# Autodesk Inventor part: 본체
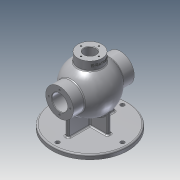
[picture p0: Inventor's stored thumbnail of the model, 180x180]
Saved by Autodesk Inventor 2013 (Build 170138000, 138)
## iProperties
Created: 2020-08
Part Number: 본체
Material: 알루미늄 6061
Document SubType Name: Modeling
Designer: 19
Density: 2.71 g/cm^3
Mass: 1759.16 g
Surface Area: 1342.42 cm^2
Volume: 649.136 cm^3
Author: 19
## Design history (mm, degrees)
sketch "스케치1"
  geometry: L1 (17.289, -50.101)-(-17.289, 50.101); A1 r 53 centre (0, 0) between (17.289, -50.101) and (-17.289, 50.101); 1 further point
  constraints: 2 end point, 2 point on circle, 1 centre point, 1 coincident, 1 midpoint
  dimensions: "d0" = 53 radius of A1
revolve "회전1" sketch "스케치1" stored, may be unused: angle "d1" = 90 deg
node "작업 평면1"
sketch "스케치2"
  geometry: C1 r 31 at (0, 0); 1 further point
  constraints: 1 centre point, 1 coincident
  dimensions: "d3" = 62 diameter of C1
extrude "돌출1" join sketch "스케치2" stored distance "d4" = 10; taper "d5" = 0 deg
sketch "스케치3"
  geometry: C1 r 31 at (0, 0) reference; C2 r 17.5 at (0, 0)
  constraints: 1 centre point, 1 coincident
  dimensions: "d6" = 35 diameter of C2
extrude "돌출2" cut sketch "스케치3" stored distance "d8" = 10; taper "d9" = 0 deg
sketch "스케치4" dims "d11" = 48
  geometry: C1 r 17.5 at (0, 0) reference; C2 r 31 at (0, 0) reference; 2 further points
  constraints: 3 coincident, 2 vertical alignment, 2 other
hole "구멍1" sketch "스케치4" at (0, 24) diameter "d12" = 3.242; stored, may be unused: countersink angle "d16" = 90 deg, drill point angle "d18" = 118 deg; dims "d13" = 12, "d14" = 4, "d15" = 2, "d17" = 15
sketch "스케치5"
  geometry: L1 (-68, 31)-(-42.988, 31) reference; L2 (42.988, 31)-(68, 31) reference; L3 (68, 31)-(68, 25.621) reference; L4 (68, 25.621)-(53, 25.621) reference; L5 (53, 25.621)-(52.026, 24) reference; L6 (52.026, 24)-(53, 22.379) reference; L7 (53, 22.379)-(68, 22.379) reference; L8 (68, 22.379)-(68, 17.5) reference; L9 (68, 17.5)-(-68, 17.5) reference; L10 (-68, 17.5)-(-68, 22.379) reference; L11 (-68, 22.379)-(-53, 22.379) reference; L12 (-53, 22.379)-(-52.026, 24) reference; L13 (-52.026, 24)-(-53, 25.621) reference; L14 (-53, 25.621)-(-68, 25.621) reference; L15 (-68, 25.621)-(-68, 31) reference; L16 (-42.988, -31)-(-68, -31) reference; L17 (-68, -31)-(-68, -25.621) reference; L18 (-68, -25.621)-(-53, -25.621) reference; L19 (-53, -25.621)-(-52.026, -24) reference; L20 (-52.026, -24)-(-53, -22.379) reference; L21 (-53, -22.379)-(-68, -22.379) reference; L22 (-68, -22.379)-(-68, -17.5) reference; L23 (-68, -17.5)-(68, -17.5) reference; L24 (68, -17.5)-(68, -22.379) reference; L25 (68, -22.379)-(53, -22.379) reference; L26 (53, -22.379)-(52.026, -24) reference; L27 (52.026, -24)-(53, -25.621) reference; L28 (53, -25.621)-(68, -25.621) reference; L29 (68, -25.621)-(68, -31) reference; L30 (68, -31)-(42.988, -31) reference; L31 (19.526, -38.311)-(-19.526, 38.311); A1 r 53 centre (0, 0) between (42.988, 31) and (0, 53) reference; A2 r 53 centre (0, 0) between (0, 53) and (-42.988, 31) reference; A3 r 53 centre (0, 0) between (-42.988, -31) and (0, -53) reference; A4 r 53 centre (0, 0) between (0, -53) and (42.988, -31) reference; A5 r 43 centre (0, 0) between (19.526, -38.311) and (-19.526, 38.311); 1 further point
  constraints: 2 end point, 2 point on circle, 1 centre point, 1 coincident, 1 midpoint
  dimensions: "d22" = 43 radius of A5
revolve "회전2" sketch "스케치5" stored, may be unused: angle "d23" = 90 deg
sketch "스케치6"
  geometry: L1 (-68, 31)-(-42.988, 31) reference; L2 (42.988, 31)-(68, 31) reference; L3 (68, 31)-(68, 25.621) reference; L4 (68, 25.621)-(53, 25.621) reference; L5 (53, 25.621)-(52.026, 24) reference; L6 (52.026, 24)-(53, 22.379) reference; L7 (53, 22.379)-(68, 22.379) reference; L8 (68, 22.379)-(68, 17.5) reference; L9 (68, 17.5)-(39.278, 17.5) reference; L10 (-39.278, 17.5)-(-68, 17.5) reference; L11 (-68, 17.5)-(-68, 22.379) reference; L12 (-68, 22.379)-(-53, 22.379) reference; L13 (-53, 22.379)-(-52.026, 24) reference; L14 (-52.026, 24)-(-53, 25.621) reference; L15 (-53, 25.621)-(-68, 25.621) reference; L16 (-68, 25.621)-(-68, 31) reference; L17 (-42.988, -31)-(-68, -31) reference; L18 (-68, -31)-(-68, -25.621) reference; L19 (-68, -25.621)-(-53, -25.621) reference; L20 (-53, -25.621)-(-52.026, -24) reference; L21 (-52.026, -24)-(-53, -22.379) reference; L22 (-53, -22.379)-(-68, -22.379) reference; L23 (-68, -22.379)-(-68, -17.5) reference; L24 (-68, -17.5)-(-39.278, -17.5) reference; L25 (39.278, -17.5)-(68, -17.5) reference; L26 (68, -17.5)-(68, -22.379) reference; L27 (68, -22.379)-(53, -22.379) reference; L28 (53, -22.379)-(52.026, -24) reference; L29 (52.026, -24)-(53, -25.621) reference; L30 (53, -25.621)-(68, -25.621) reference; L31 (68, -25.621)-(68, -31) reference; L32 (68, -31)-(42.988, -31) reference; L33 (-68, -17.5)-(-68, 17.5) reference; L34 (68, 17.5)-(68, -17.5) reference; L35 (-68, 0)-(68, 0); L36 (-52, 0)-(-52, 18.5); L37 (-52, 18.5)-(-50.25, 18.5); L38 (-50.25, 18.5)-(-50.25, 0); A1 r 53 centre (0, 0) between (42.988, 31) and (0, 53) reference; A2 r 53 centre (0, 0) between (0, 53) and (-42.988, 31) reference; A3 r 43 centre (0, 0) between (39.278, 17.5) and (0, 43) reference; A4 r 43 centre (0, 0) between (0, 43) and (-39.278, 17.5) reference; A5 r 43 centre (0, 0) between (-39.278, -17.5) and (0, -43) reference; A6 r 43 centre (0, 0) between (0, -43) and (39.278, -17.5) reference; A7 r 53 centre (0, 0) between (-42.988, -31) and (0, -53) reference; A8 r 53 centre (0, 0) between (0, -53) and (42.988, -31) reference; 1 further point
  constraints: 8 end point, 2 midpoint, 2 perpendicular, 2 point on line, 1 parallel
  dimensions: "d24" = 37 diameter of L37 L35; "d26" = 1.75 distance of L36.end L37.end; "d27" = 16 distance between parallel lines of L36 L33
revolve "회전3" sketch "스케치6" stored, may be unused: angle "d28" = 90 deg
node "작업 평면2"
sketch "스케치7"
  geometry: C1 r 27 at (0, 0); 1 further point
  constraints: 1 centre point, 1 coincident
  dimensions: "d30" = 54 diameter of C1
extrude "돌출3" join sketch "스케치7" stored distance "d31" = 10; taper "d32" = 0 deg
sketch "스케치8"
  geometry: C1 r 27 at (0, 0) reference; C2 r 13 at (0, 0)
  constraints: 1 centre point, 1 coincident
  dimensions: "d33" = 26 diameter of C2
extrude "돌출4" cut sketch "스케치8" stored distance "d34" = 10; taper "d35" = 0 deg
sketch "스케치9" dims "d36" = 40
  geometry: C1 r 13 at (0, 0) reference; C2 r 27 at (0, 0) reference; 2 further points
  constraints: 3 coincident, 2 vertical alignment, 2 other
hole "구멍2" sketch "스케치9" at (0, 20) diameter "d37" = 3.242; stored, may be unused: countersink angle "d41" = 90 deg, drill point angle "d43" = 118 deg; dims "d38" = 12, "d39" = 4, "d40" = 2, "d42" = 15
node "작업 평면3"
sketch "스케치10"
  geometry: C1 r 85 at (0, 0); 1 further point
  constraints: 1 centre point, 1 coincident
  dimensions: "d48" = 170 diameter of C1
extrude "돌출5" join sketch "스케치10" distance "d49" = 10; taper "d50" = 0 deg
sketch "스케치11"
  geometry: L1 (-31, 42.988)-(31, 42.988) reference; L2 (31, -42.988)-(-31, -42.988) reference; L3 (31, 68)-(-31, 68) reference; L4 (-31, 42.988)-(31, 42.988) reference; L5 (31, -68)-(-31, -68) reference; L6 (31, -42.988)-(-31, -42.988) reference; L7 (-43, 4)-(43, 4); L8 (43, 4)-(43, -4); L9 (43, -4)-(-43, -4); L10 (-43, -4)-(-43, 4); C1 r 85 at (0, 0) reference; C2 r 85 at (0, 0) reference; C3 r 27 at (0, 0) reference; C4 r 85 at (0, 0) reference; 5 further points
  constraints: 8 end point, 2 midpoint, 2 parallel, 1 horizontal, 1 horizontal alignment, 1 perpendicular, 1 vertical alignment, 1 other
  dimensions: "d51" = 86 distance of L8.end L9.end; "d53" = 8 distance of L9.end L7.start
extrude "돌출6" join sketch "스케치11" stored distance "d54" = 10; taper "d55" = 0 deg
sketch "스케치12"
  geometry: L1 (-4, 52)-(4, 52); L2 (4, 52)-(4, -52); L3 (4, -52)-(-4, -52); L4 (-4, -52)-(-4, 52); C1 r 85 at (0, 0) reference; 2 further points
  constraints: 8 end point, 2 midpoint, 2 parallel, 1 horizontal, 1 horizontal alignment, 1 perpendicular, 1 vertical alignment
  dimensions: "d56" = 104 distance of L1.end L2.end; "d58" = 8 distance of L1.start L1.end
extrude "돌출7" join sketch "스케치12" stored distance "d59" = 10; taper "d60" = 0 deg
node "작업 평면4"
chamfer "모따기1" distance "d77" = 1; stored, may be unused: second distance "d78" = 2, angle "d79" = 45 deg
fillet "모깎기1" dims "d80" = 3
fillet "모깎기2" dims "d81" = 3
fillet "모깎기3" dims "d82" = 3
fillet "모깎기4" dims "d83" = 3
fillet "모깎기5" dims "d84" = 3
node "작업 평면5"
sketch "스케치15"
  geometry: L1 (-27, 65)-(27, 65) reference; L2 (-27, 47.286)-(27, 47.286) reference; L3 (-27, 65)-(-27, 47.286) reference; L4 (27, 65)-(27, 47.286) reference; 2 further points
  constraints: 1 other
  dimensions: "d86" = 9 distance from line of point (0, 56) L1; "d87" = 27 distance from line of point (0, 56) L3
feature "엠보싱2" sketch "스케치15" dims "d88" = 0.5, "d89" = 0
sketch "스케치16" dims "d91" = 145
  geometry: C1 r 82 at (0, 0) reference; 2 further points
  constraints: 2 vertical alignment, 1 coincident, 2 other
hole "구멍4" sketch "스케치16" at (0, 72.5) diameter "d92" = 9; stored, may be unused: countersink angle "d96" = 90 deg, drill point angle "d98" = 118 deg; dims "d93" = 12, "d94" = 4, "d95" = 2, "d97" = 15
node "솔리드1"
mirror "대칭1"
pattern_circular "원형 패턴1" dims angle "d20" = 360 deg
mirror "대칭2"
pattern_circular "원형 패턴2" dims angle "d45" = 360 deg
pattern_circular "원형 패턴4" dims angle "d100" = 360 deg
node "투영된 루프1"
node "투영된 루프2"
node "투영된 루프3"
node "투영된 루프4"
node "절단 모서리 투영1"
node "절단 모서리 투영2"
node "절단 모서리 투영3"
node "절단 모서리 투영4"
other parameters: "d2" = -68, "d29" = 65, "d47" = -85, "d61" = -134.5, "d85" = -37.25
